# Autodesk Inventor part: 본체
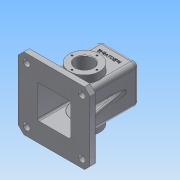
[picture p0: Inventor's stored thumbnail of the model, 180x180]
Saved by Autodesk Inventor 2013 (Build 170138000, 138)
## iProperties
Created: 2016-02
Part Number: 본체
Material: 알루미늄 6061
Document SubType Name: Modeling
Designer: Administrator
Density: 2.71 g/cm^3
Mass: 932.819 g
Surface Area: 1043.33 cm^2
Volume: 344.214 cm^3
Author: Administrator
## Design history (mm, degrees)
sketch "스케치1"
  geometry: L1 (-60, -35)-(60, -35); L2 (60, -35)-(60, 35); L3 (60, 35)-(-60, 35); L4 (-60, 35)-(-60, -35); L5 (-60, -35)-(60, 35); L6 (60, -35)-(-60, 35); 1 further point
  constraints: 12 end point, 2 midpoint, 2 parallel, 1 horizontal, 1 perpendicular
  dimensions: "d0" = 120 distance of L3.end L2.end; "d1" = 70 distance of L2.end L1.end
extrude "돌출1" new body sketch "스케치1" stored distance "d2" = 70; taper "d3" = 0 deg
sketch "스케치2"
  geometry: L1 (-50, 65)-(-60, 65); L2 (-60, 65)-(-60, -65); L3 (-60, -65)-(-50, -65); L4 (-50, -65)-(-50, 65); L5 (-60, -35)-(-60, 35) reference; 2 further points
  constraints: 8 end point, 2 midpoint, 2 parallel, 1 horizontal, 1 perpendicular
  dimensions: "d4" = 10 distance of L3.end L2.end; "d5" = 130 distance of L2.end L1.end
extrude "돌출2" join sketch "스케치2" stored distance "d6" = 130; taper "d7" = 0 deg
feature "쉘1" dims "d23" = 10, "d24" = 5
sketch "스케치3"
  geometry: L1 (35, -50)-(-35, -50) reference; L2 (-35, 60)-(-35, -50) reference; L3 (-35, 60)-(35, 60) reference; L4 (35, -50)-(35, 60) reference; L5 (-65, -50)-(65, -50) reference; L6 (65, -60)-(65, -50) reference; L7 (-65, -60)-(65, -60) reference; L8 (-65, -50)-(-65, -60) reference; L9 (50, -50)-(35, 35.069); L10 (65, -50)-(65, 24.453); 1 further point
  constraints: 4 end point, 2 point on line, 1 parallel
  dimensions: "d8" = 15 distance of L5.end L9.start; "d9" = 10 deg angle of L10 L9
feature "리브1" sketch "스케치3" dims "d10" = 1, "d11" = 10, "d12" = 0, "d13" = 0, "d14" = 1, "d15" = 1
sketch "스케치4"
  geometry: L1 (70, 0)-(70, -110) reference; L2 (5, -120)-(65, -120) reference; L3 (70, -110)-(0, -110) reference; L4 (0, 0)-(0, -110) reference; L5 (70, 0)-(0, 0) reference; L6 (70, -110)-(70, 0) reference; C1 r 27.5 at (35, -65)
  constraints: 1 centre point
  dimensions: "d16" = 55 diameter of C1; "d71" = 55 distance from line of C1.centre L2; "d72" = 35 distance from line of L1 C1.centre
extrude "돌출3" join sketch "스케치4" distance "d17" = 13; taper "d18" = 0 deg
sketch "스케치5"
  geometry: C1 r 20 at (35, -35); 1 further point
  constraints: 1 centre point, 1 coincident
  dimensions: "d19" = 40 diameter of C1
extrude "돌출4" join sketch "스케치5" distance "d20" = 10; taper "d21" = -10 deg
fillet "모깎기1" dims "d22" = 3
sketch "스케치6"
  geometry: C1 r 27.5 at (30, 60); 1 further point
  constraints: 1 centre point, 1 coincident
  dimensions: "d25" = 55 diameter of C1
extrude "돌출5" join sketch "스케치6" distance "d26" = 7; taper "d27" = -45 deg
sketch "스케치7"
  geometry: C1 r 27.5 at (0, 0) reference; C2 r 16 at (0, 0)
  constraints: 1 centre point, 1 coincident
  dimensions: "d28" = 32 diameter of C2
extrude "돌출6" cut sketch "스케치7" stored distance "d29" = 7; taper "d30" = 0 deg
sketch "스케치8"
  geometry: C1 r 18.237 at (0, 0) reference; C2 r 14 at (0, 0)
  constraints: 1 centre point, 1 coincident
  dimensions: "d31" = 28 diameter of C2
extrude "돌출7" cut sketch "스케치8" distance "d32" = 4; taper "d33" = 0 deg
sketch "스케치9"
  geometry: C1 r 14 at (0, 0) reference; C2 r 10.5 at (0, 0)
  constraints: 1 centre point, 1 coincident
  dimensions: "d34" = 21 diameter of C2
extrude "돌출8" cut sketch "스케치9" stored distance "d35" = 4; taper "d36" = 0 deg
sketch "스케치10"
  geometry: C1 r 16 at (0, 0) reference; 1 further point
  constraints: 1 vertical alignment
  dimensions: "d37" = 22.5 distance of point (0, 22.5) C1.centre
hole "구멍1" sketch "스케치10" at (0, 22.5) diameter "d38" = 3.242; stored, may be unused: countersink angle "d42" = 90 deg, drill point angle "d44" = 118 deg; dims "d39" = 8, "d40" = 4, "d41" = 2, "d43" = 10
sketch "스케치11"
  geometry: L1 (0, 0)-(130, 0) reference; C1 r 6 at (15, -15); 1 further point
  constraints: 1 centre point
  dimensions: "d48" = 12 diameter of C1; "d49" = 50 horizontal distance of point (65, -65) C1.centre; "d50" = 15 distance from line of L1 C1.centre
extrude "돌출9" cut sketch "스케치11" stored distance "d51" = 4; taper "d52" = 0 deg
chamfer "모따기1" distance "d53" = 10; stored, may be unused: second distance "d54" = 2, angle "d55" = 45 deg
fillet "모깎기2" dims "d56" = 8
fillet "모깎기3" dims "d57" = 0.5
chamfer "모따기2" distance "d58" = 1; stored, may be unused: second distance "d59" = 2, angle "d60" = 45 deg
fillet "모깎기4" dims "d61" = 3
fillet "모깎기5" dims "d62" = 3
fillet "모깎기6" dims "d63" = 3
fillet "모깎기7" dims "d64" = 3
fillet "모깎기8" dims "d65" = 3
fillet "모깎기9" dims "d66" = 8
sketch "스케치12"
  geometry: L1 (35, -42)-(35, 57) reference; L2 (-18.237, 75)-(18.237, 75) reference; 1 further point
  constraints: 1 other
  dimensions: "d67" = 35 distance from line of L1 point (0, 45); "d68" = 30 distance from line of L2 point (0, 45)
feature "엠보싱1" sketch "스케치12" dims "d69" = 0.5, "d70" = 0
fillet "모깎기10" dims "d73" = 0.5
node "솔리드1"
mirror "대칭1"
mirror "대칭2"
mirror "대칭3"
pattern_circular "원형 패턴1" dims angle "d46" = 360 deg
mirror "대칭4"
mirror "대칭5"
mirror "대칭6"
node "투영된 루프1"
node "투영된 루프2"
node "투영된 루프3"
